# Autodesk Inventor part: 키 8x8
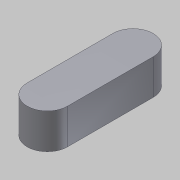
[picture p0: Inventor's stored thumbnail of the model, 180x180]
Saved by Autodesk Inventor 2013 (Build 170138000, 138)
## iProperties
Company: 한국ATC센터
Created: 2014-11
Part Number: 키 8x8
Document SubType Name: Modeling
Designer: KYOUNG IL JANG
Density: 7.86 g/cm^3
Material: 강, 연강
Mass: 10.2483 g
Surface Area: 7.8646 cm^2
Volume: 1.30386 cm^3
Author: KYOUNG IL JANG
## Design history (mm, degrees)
sketch "스케치1"
  geometry: L1 (28.264, -14)-(28.264, -31) reference; L2 (20.264, -31)-(20.264, -14) reference; A1 r 4 centre (24.264, -31) between (20.264, -31) and (28.264, -31) reference; A2 r 4 centre (24.264, -14) between (28.264, -14) and (20.264, -14) reference; 1 further point
extrude "돌출1" new body sketch "스케치1" distance "d0" = 7; taper "d1" = 0 deg
node "솔리드1"
node "참조1"
